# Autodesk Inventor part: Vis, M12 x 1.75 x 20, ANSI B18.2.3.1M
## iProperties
Shininess: 64.0
Length Units: 11269
Angle Units: 11279
Time Units: 11290
Mass Units: 11283
Length Display Precision: 3
Angle Display Precision: 2
Compacted: True
Part Number: Vis, M12 x 1.75 x 20, ANSI B18.2.3.1M
Document SubType Name: Modeling
Created: 2005-01
Material: Par défaut
Designer: LEGERET Philippe
Catalog Web Link: www.traceparts.com
Description: Vis à métaux - Tête hexagonale, M12 x 1.75 x 20, ANSI B18.2.3.1M
Density: 0.0
Volumn: 0.0
Area: 0.0
PropertySet Name: Model Information
Control State: 0
Master: False
Checked Out: False
Author: Trace Parts S.A.
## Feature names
1. Base1
